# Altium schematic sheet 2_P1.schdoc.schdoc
size 309 x 223 mm; Symbol: A4_Schematic_0605; Device: A4_Schematic_0605; @Project Name: MDIO-Board_Rev_01(0124); @Page Count: 10; @Update Date: 2024-06-05; @Create Date: 2024-05-19; @Schematic Name: Schematic1; @Page No: 1; @Page Name: P1
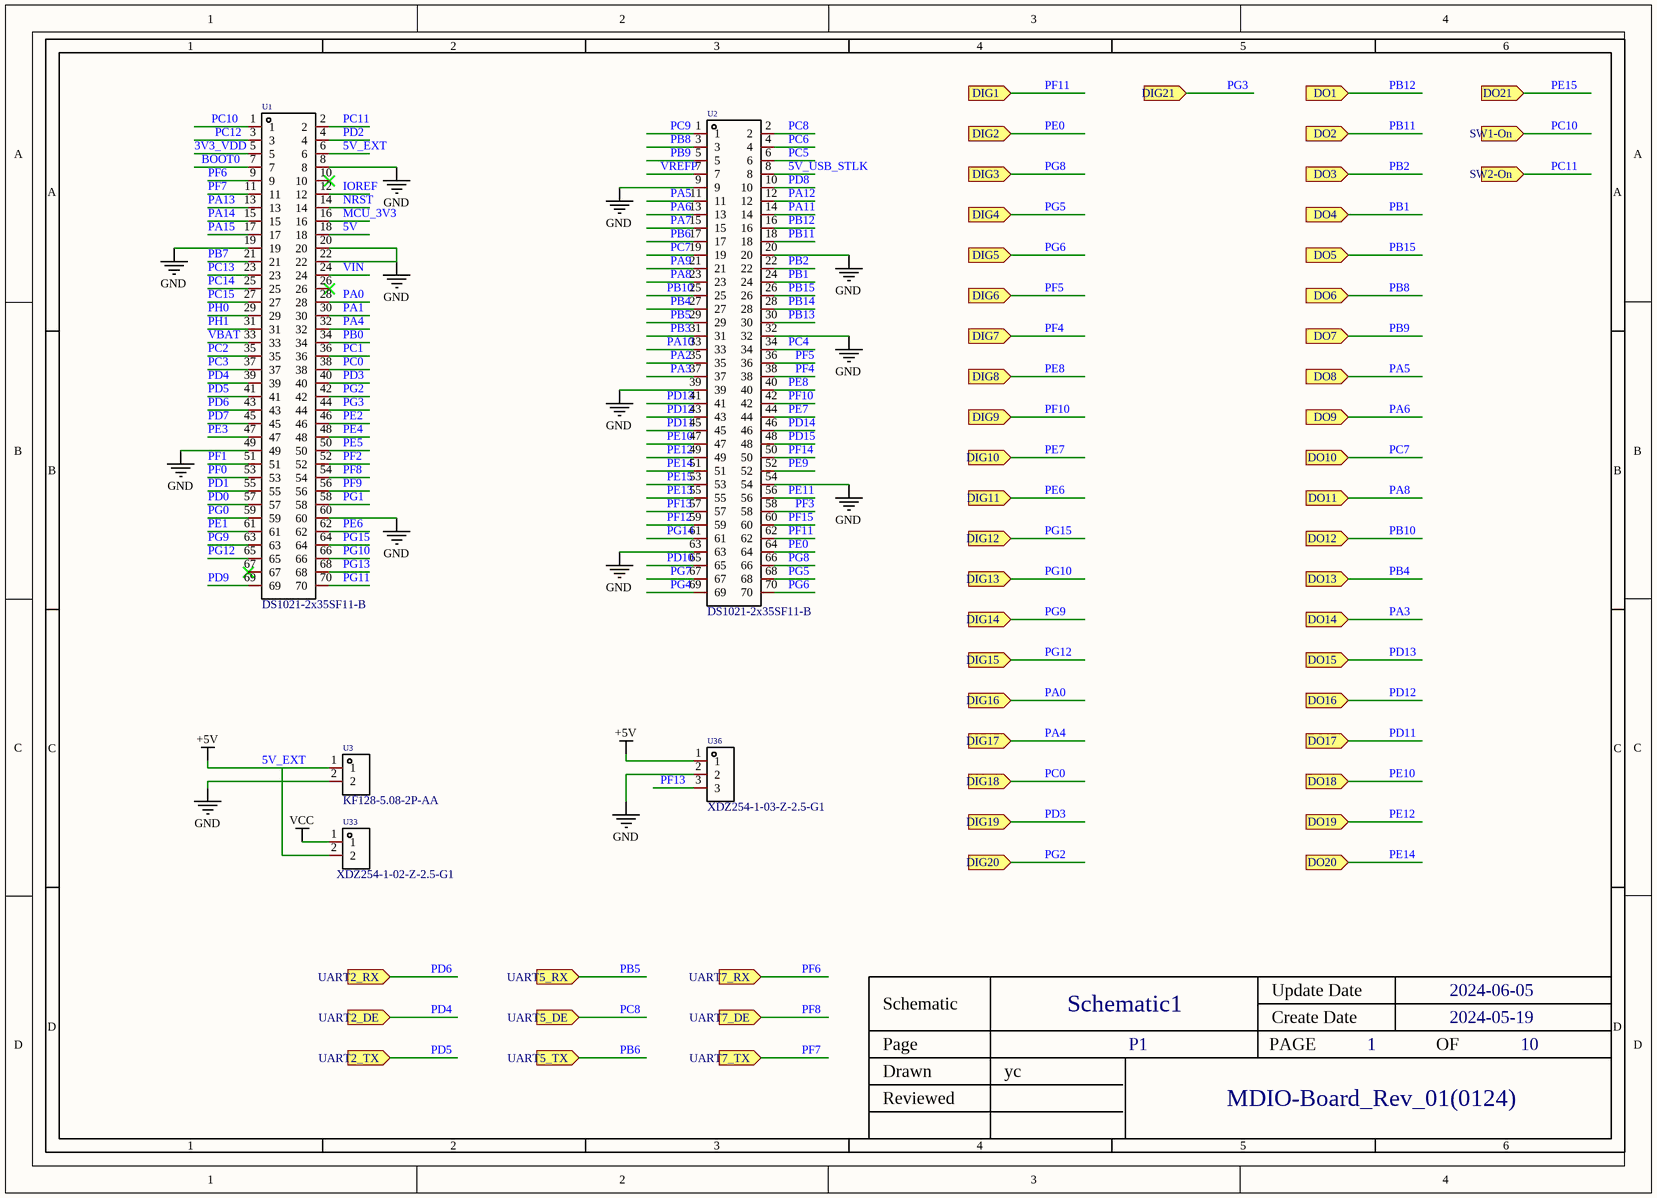
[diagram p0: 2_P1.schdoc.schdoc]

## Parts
U1  DS1021-2x35SF11-B  [HDR-TH_70P-P2.54-V-M-R2-C35-S2.54]
U2  DS1021-2x35SF11-B  [HDR-TH_70P-P2.54-V-M-R2-C35-S2.54]
U3  KF128-5.08-2P-AA  [CONN-TH_P5.08_KF128-5.08-2P]
U33  XDZ254-1-02-Z-2.5-G1  [HDR-TH_2P-P2.54-V-M]
U36  XDZ254-1-03-Z-2.5-G1  [HDR-TH_3P-P2.54-V-M-1]

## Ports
DIG1 (in), DIG2 (in), DIG3 (in), DIG4 (in), DIG5 (in), DIG6 (in), DIG7 (in), DIG8 (in), DIG9 (in), DIG10 (in), DIG11 (in), DIG12 (in), DIG13 (in), DIG14 (in), DIG15 (in), DIG16 (in), DIG17 (in), DIG18 (in), DIG19 (in), DIG20 (in), DIG21 (in), DO1 (in), DO2 (in), DO3 (in), DO4 (in), DO5 (in), DO6 (in), DO7 (in), DO8 (in), DO9 (in), DO10 (in), DO11 (in), DO12 (in), DO13 (in), DO14 (in), DO15 (in), DO16 (in), DO17 (in), DO18 (in), DO19 (in), DO20 (in), DO21 (in), SW1-On (in), SW2-On (in), UART2_DE (in), UART2_RX (in), UART2_TX (in), UART5_DE (in), UART5_RX (in), UART5_TX (in), UART7_DE (in), UART7_RX (in), UART7_TX (in)

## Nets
5V_EXT: U1.6 U3.1 U33.2 U36.1  [also labelled +5V]
GND: U1.8 U1.19 U1.20 U1.22 U1.49 U1.60 U2.9 U2.20 U2.32 U2.39 U2.54 U2.63 U3.2 U36.2
VCC: U33.1
3V3_VDD: U1.5
5V: U1.18
5V_USB_STLK: U2.8
BOOT0: U1.7
IOREF: U1.12
MCU_3V3: U1.16
NRST: U1.14
PA0: U1.28 ; port DIG16
PA1: U1.30
PA2: U2.35
PA3: U2.37 ; port DO14
PA4: U1.32 ; port DIG17
PA5: U2.11 ; port DO8
PA6: U2.13 ; port DO9
PA7: U2.15
PA8: U2.23 ; port DO11
PA9: U2.21
PA10: U2.33
PA11: U2.14
PA12: U2.12
PA13: U1.13
PA14: U1.15
PA15: U1.17
PB0: U1.34
PB1: U2.24 ; port DO4
PB2: U2.22 ; port DO3
PB3: U2.31
PB4: U2.27 ; port DO13
PB5: U2.29 ; port UART5_RX
PB6: U2.17 ; port UART5_TX
PB7: U1.21
PB8: U2.3 ; port DO6
PB9: U2.5 ; port DO7
PB10: U2.25 ; port DO12
PB11: U2.18 ; port DO2
PB12: U2.16 ; port DO1
PB13: U2.30
PB14: U2.28
PB15: U2.26 ; port DO5
PC0: U1.38 ; port DIG18
PC1: U1.36
PC2: U1.35
PC3: U1.37
PC4: U2.34
PC5: U2.6
PC6: U2.4
PC7: U2.19 ; port DO10
PC8: U2.2 ; port UART5_DE
PC9: U2.1
PC10: U1.1 ; port SW1-On
PC11: U1.2 ; port SW2-On
PC12: U1.3
PC13: U1.23
PC14: U1.25
PC15: U1.27
PD0: U1.57
PD1: U1.55
PD2: U1.4
PD3: U1.40 ; port DIG19
PD4: U1.39 ; port UART2_DE
PD5: U1.41 ; port UART2_TX
PD6: U1.43 ; port UART2_RX
PD7: U1.45
PD8: U2.10
PD9: U1.69
PD10: U2.65
PD11: U2.45 ; port DO17
PD12: U2.43 ; port DO16
PD13: U2.41 ; port DO15
PD14: U2.46
PD15: U2.48
PE0: U2.64 ; port DIG2
PE1: U1.61
PE2: U1.46
PE3: U1.47
PE4: U1.48
PE5: U1.50
PE6: U1.62 ; port DIG11
PE7: U2.44 ; port DIG10
PE8: U2.40 ; port DIG8
PE9: U2.52
PE10: U2.47 ; port DO18
PE11: U2.56
PE12: U2.49 ; port DO19
PE13: U2.55
PE14: U2.51 ; port DO20
PE15: U2.53 ; port DO21
PF0: U1.53
PF1: U1.51
PF2: U1.52
PF3: U2.58
PF4: U2.38 ; port DIG7
PF5: U2.36 ; port DIG6
PF6: U1.9 ; port UART7_RX
PF7: U1.11 ; port UART7_TX
PF8: U1.54 ; port UART7_DE
PF9: U1.56
PF10: U2.42 ; port DIG9
PF11: U2.62 ; port DIG1
PF12: U2.59
PF13: U2.57 U36.3
PF14: U2.50
PF15: U2.60
PG0: U1.59
PG1: U1.58
PG2: U1.42 ; port DIG20
PG3: U1.44 ; port DIG21
PG4: U2.69
PG5: U2.68 ; port DIG4
PG6: U2.70 ; port DIG5
PG7: U2.67
PG8: U2.66 ; port DIG3
PG9: U1.63 ; port DIG14
PG10: U1.66 ; port DIG13
PG11: U1.70
PG12: U1.65 ; port DIG15
PG13: U1.68
PG14: U2.61
PG15: U1.64 ; port DIG12
PH0: U1.29
PH1: U1.31
VBAT: U1.33
VIN: U1.24
VREFP: U2.7

Not connected (* = marked no-connect by the designer): U1 10* 26* 67*

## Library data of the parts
U1 U2 = DS1021-2x35SF11-B: Manufacturer: CONNFLY; Add into BOM: yes; Pin Structure: 2x35P; Pitch: 2.54mm; Description: Pin Structure:2x35P Pitch:2.54mm Mounting Type:Straight Number of Rows:双排 Number of Pins:70P
U3 = KF128-5.08-2P-AA: Manufacturer: KEFA(科发); Add into BOM: yes; Structure: 1x2P; Pitch: 5.08mm; Current Rating (Max): 24A; Voltage Rating (Max): 250V; Wire Gauge - AWG: 12~22; Wire Gauge - mm2: 2.5; Number of PINs Per Row: 2; Description: Structure:1x2P Pitch:5.08mm Color:Green Mounting Style:Straight Current Rating (Max):24A Voltage Rating (Max):250V Number of Pins:2P Number of Rows:1 Wire Gauge - AWG:12~22 Wire Gauge - AWG:12~22 Wire Gauge - mm2:2.5 Wire Gauge - mm2:2.5 Number of PINs Pe
U33 = XDZ254-1-02-Z-2.5-G1: Manufacturer: XUNDA(讯答); Add into BOM: yes; Pin Structure: 1x2P; Pitch: 2.54mm; Circluar Pins/Square Pins: Square Pins; Current Rating (Max): 3A; Description: Pin Structure:1x2P Pitch:2.54mm Circluar Pins/Square Pins:Square Pins Mounting Type:Straight Number of Rows:Plugin Number of Pins:2P Current Rating (Max):3A Length of Mating Pin:6mm Insulation Height:2.5mm Length of End Connection Pin:3mm Operating Temper
U36 = XDZ254-1-03-Z-2.5-G1: Manufacturer: XUNDA(讯答); Add into BOM: yes; Pin Structure: 1x3P; Pitch: 2.54mm; Circluar Pins/Square Pins: Square Pins; Current Rating (Max): 3A; Description: Pin Structure:1x3P Pitch:2.54mm Circluar Pins/Square Pins:Square Pins Mounting Type:Straight Number of Rows:Plugin Number of Pins:3P Current Rating (Max):3A Length of Mating Pin:6mm Insulation Height:2.5mm Length of End Connection Pin:3mm Operating Temper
